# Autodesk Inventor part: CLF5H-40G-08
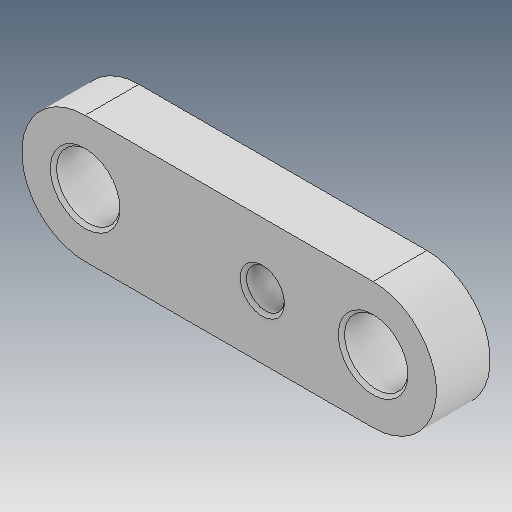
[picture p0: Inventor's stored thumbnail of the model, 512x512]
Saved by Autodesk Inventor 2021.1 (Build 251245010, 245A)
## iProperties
Created: 2013-04
Part Number: CLF5H-40G-08
Material: Ogólny
Document SubType Name: Modeling
Designer: user
Density: 1 g/cm^3
Appearance: Domyślna
Author: user
Revision Number: ÈÎºÎ
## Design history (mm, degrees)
feature "µ¹½Ç1"
node "Bryła1"
